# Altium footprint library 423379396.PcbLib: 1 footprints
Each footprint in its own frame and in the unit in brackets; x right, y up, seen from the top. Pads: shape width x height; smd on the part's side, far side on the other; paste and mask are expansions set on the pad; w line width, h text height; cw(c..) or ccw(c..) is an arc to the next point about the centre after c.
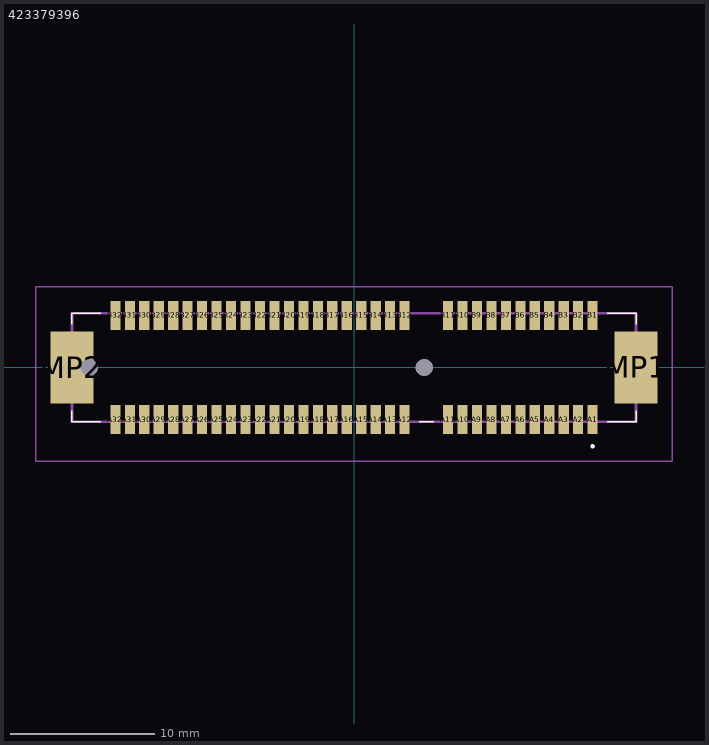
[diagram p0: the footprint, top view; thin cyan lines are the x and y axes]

## 423379396 [mm]
pads (68):
  rect 0.7x2 smd: A1(16.5,-3.6) A2(15.5,-3.6) A3(14.5,-3.6) A4(13.5,-3.6) A5(12.5,-3.6) A6(11.5,-3.6) A7(10.5,-3.6) A8(9.5,-3.6) A9(8.5,-3.6) A10(7.5,-3.6) A11(6.5,-3.6) A12(3.5,-3.6) A13(2.5,-3.6) A14(1.5,-3.6) A15(0.5,-3.6) A16(-0.5,-3.6) A17(-1.5,-3.6) A18(-2.5,-3.6) A19(-3.5,-3.6) A20(-4.5,-3.6) A21(-5.5,-3.6) A22(-6.5,-3.6) A23(-7.5,-3.6) A24(-8.5,-3.6) A25(-9.5,-3.6) A26(-10.5,-3.6) A27(-11.5,-3.6) A28(-12.5,-3.6) A29(-13.5,-3.6) A30(-14.5,-3.6) A31(-15.5,-3.6) A32(-16.5,-3.6) B1(16.5,3.6) B2(15.5,3.6) B3(14.5,3.6) B4(13.5,3.6) B5(12.5,3.6) B6(11.5,3.6) B7(10.5,3.6) B8(9.5,3.6) B9(8.5,3.6) B10(7.5,3.6) B11(6.5,3.6) B12(3.5,3.6) B13(2.5,3.6) B14(1.5,3.6) B15(0.5,3.6) B16(-0.5,3.6) B17(-1.5,3.6) B18(-2.5,3.6) B19(-3.5,3.6) B20(-4.5,3.6) B21(-5.5,3.6) B22(-6.5,3.6) B23(-7.5,3.6) B24(-8.5,3.6) B25(-9.5,3.6) B26(-10.5,3.6) B27(-11.5,3.6) B28(-12.5,3.6) B29(-13.5,3.6) B30(-14.5,3.6) B31(-15.5,3.6) B32(-16.5,3.6)
  round 0.6 hole 1.2 unplated: MH1(4.85,0) MH3(-18.3,0)
  rect 3x5 smd: MP1(19.5,0) MP2(-19.5,0)
Top Overlay:
  lines w0.1: -19.5,-3.75 -19.5,-3 ; -19.5,-3.75 -19.5,-3.75 ; -19.5,-3.75 -19.5,-3 ; -19.5,-3.75 -17.5,-3.75 ; -19.5,-3.75 -17.5,-3.75 ; -19.5,-3.75 -19.5,-3.75 ; -19.5,-3 -19.5,-3 ; -19.5,3 -19.5,3 ; -19.5,3 -19.5,3.75 ; -19.5,3 -19.5,3.75 ; -19.5,3.75 -19.5,3.75 ; -19.5,3.75 -17.5,3.75 ; -19.5,3.75 -17.5,3.75 ; -19.5,3.75 -19.5,3.75 ; -17.5,-3.75 -17.5,-3.75 ; -17.5,3.75 -17.5,3.75 ; 4.5,-3.75 5.5,-3.75 ; 4.5,-3.75 5.5,-3.75 ; 4.5,-3.75 4.5,-3.75 ; 5.5,-3.75 5.5,-3.75 ; 17.5,-3.75 19.5,-3.75 ; 17.5,-3.75 19.5,-3.75 ; 17.5,-3.75 17.5,-3.75 ; 17.5,3.75 19.5,3.75 ; 17.5,3.75 17.5,3.75 ; 17.5,3.75 19.5,3.75 ; 19.5,-3.75 19.5,-3.75 ; 19.5,-3.75 19.5,-3.75 ; 19.5,-3.75 19.5,-3 ; 19.5,-3.75 19.5,-3 ; 19.5,-3 19.5,-3 ; 19.5,3 19.5,3 ; 19.5,3 19.5,3.75 ; 19.5,3 19.5,3.75 ; 19.5,3.75 19.5,3.75 ; 19.5,3.75 19.5,3.75
  lines w0.2: 16.5,-5.5 cw(c16.5,-5.45) 16.5,-5.4 ; 16.5,-5.5 16.5,-5.5 ; 16.5,-5.5 ccw(c16.5,-5.45) 16.5,-5.4 ; 16.5,-5.5 cw(c16.5,-5.45) 16.5,-5.4 ; 16.5,-5.4 16.5,-5.4 ; 16.5,-5.4 16.5,-5.4
Mechanical 15:
  lines w0.2: -19.5,-3.75 19.5,-3.75 19.5,3.75 -19.5,3.75 -19.5,-3.75
Mechanical 20:
  lines w0.1: -22,-6.5 22,-6.5 22,5.6 -22,5.6 -22,-6.5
